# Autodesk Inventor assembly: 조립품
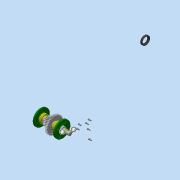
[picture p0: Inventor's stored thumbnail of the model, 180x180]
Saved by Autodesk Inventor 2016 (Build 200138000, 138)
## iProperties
Created: 2018-11
Part Number: 조립품
Material: 일반
Document SubType Name: Assembly
Designer: user
Author: user
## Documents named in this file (14)
- C:\Users\user\Desktop\481111V1014\조립품.iam
- C:\Users\user\Desktop\481111V1014\V-벨트풀리.ipt
- C:\Users\user\Desktop\481111V1014\뒤커버.ipt
- C:\Users\user\Desktop\481111V1014\멈춤나사 M4.ipt
- C:\Users\user\Desktop\481111V1014\베어링 6203.ipt
- C:\Users\user\Desktop\481111V1014\본체.ipt
- C:\Users\user\Desktop\481111V1014\볼트 M4.ipt
- C:\Users\user\Desktop\481111V1014\부시.ipt
- C:\Users\user\Desktop\481111V1014\스퍼기어.ipt
- C:\Users\user\Desktop\481111V1014\앞커버.ipt
- C:\Users\user\Desktop\481111V1014\오일 실 28 40 8.ipt
- C:\Users\user\Desktop\481111V1014\축.ipt
- C:\Users\user\Desktop\481111V1014\키 5x5x18.ipt
- C:\Users\user\Desktop\481111V1014\키 6x6x22.ipt
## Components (1 placed, 1 different names)
1. V-벨트풀리:1
